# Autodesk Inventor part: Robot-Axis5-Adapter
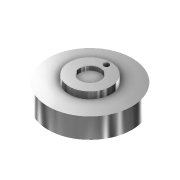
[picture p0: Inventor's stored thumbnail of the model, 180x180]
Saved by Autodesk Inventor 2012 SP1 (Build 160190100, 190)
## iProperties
Shininess: 21.0
Length Units: 11269
Angle Units: 11279
Time Units: 11290
Mass Units: 11283
Length Display Precision: 3
Angle Display Precision: 2
Created: 2001-08
Part Number: Robot-Axis5-Adapter
Document SubType Name: ﾓﾃﾞﾘﾝｸﾞ
Designer: Administrator
Density: 1 g/cm^3
Material: Default
Density: 0.0
Volumn: 0.0
Area: 0.0
PropertySet Name: Model Information
Control State: 0
Master: False
Checked Out: False
Author: Administrator
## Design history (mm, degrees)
body "Solid1"
sketch "ｽｹｯﾁ1"
  geometry: C1 r 40 at (0, 0)
  constraints: 1 centre point
  dimensions: "d0" = 80 diameter of C1
extrude "Extrusion1" new body sketch "ｽｹｯﾁ1" distance "d1" = 19.3; taper "d2" = 0 deg
sketch "ｽｹｯﾁ2"
  geometry: C1 r 40 at (0, 0) reference; C2 r 20 at (0, 0)
  constraints: 1 centre point, 1 coincident
  dimensions: "d3" = 40 diameter of C2
extrude "Extrusion2" join sketch "ｽｹｯﾁ2" distance "d4" = 6.5; taper "d5" = 0 deg
sketch "ｽｹｯﾁ3"
  geometry: L1 (0, 0)-(0, 15.75); C1 r 20 at (0, 0) reference; C2 r 10 at (0, 0); C3 r 2.5 at (0, 15.75)
  constraints: 2 centre point, 2 coincident, 2 end point, 1 vertical
  dimensions: "d6" = 20 diameter of C2; "d9" = 15.75 distance of L1.start L1.end; "d10" = 5 diameter of C3
extrude "Extrusion3" cut sketch "ｽｹｯﾁ3" distance "d7" = 4; taper "d8" = 0 deg
